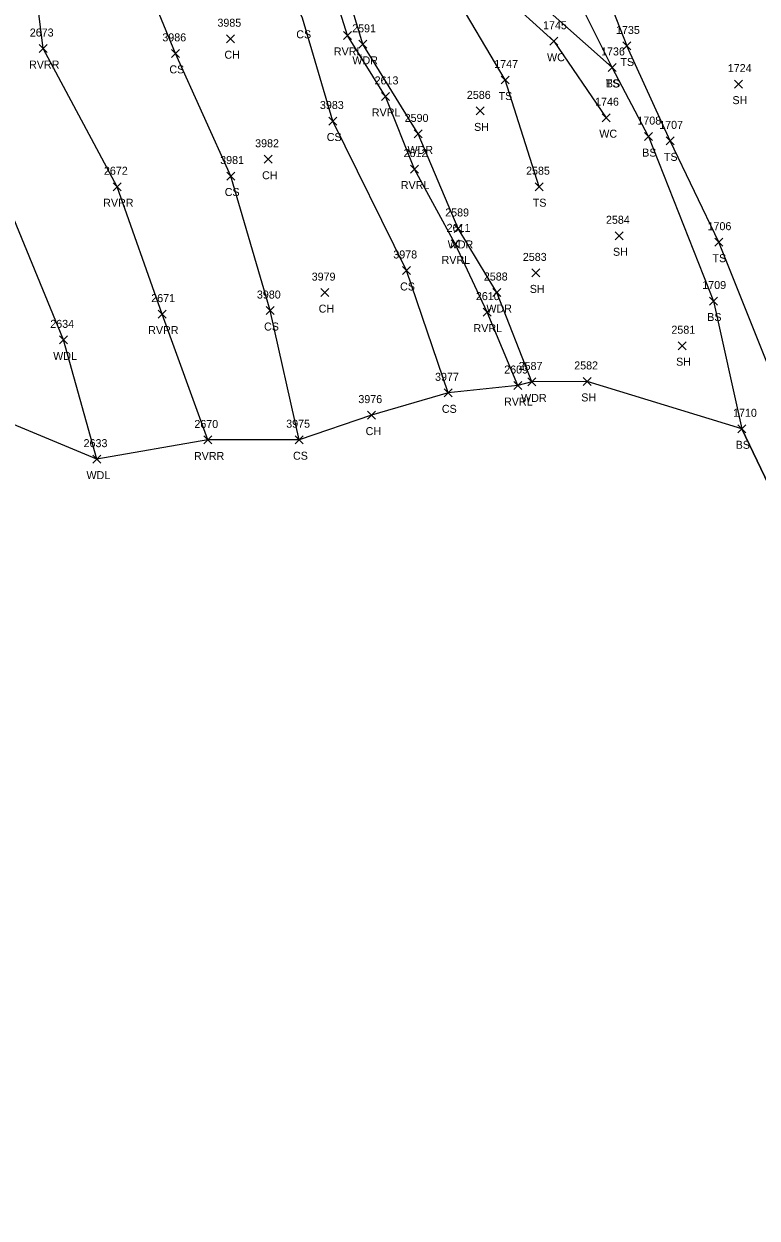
# Model space of a CAD drawing. Extents: x 1482574 to 1485769, y 580696 to 595649.
# Drawn here: x 1484896.9 to 1485080.1, y 582027 to 582325.6 of the extents above; entities that cross this region are included whole.
import ezdxf

# ---------------------------------------------------------------- set-up
doc = ezdxf.new("R2010")
doc.units = 0
for name, color, linetype in [('L_A', 7, 'Continuous'), ('L_I', 7, 'Continuous'), ('L_TIC', 7, 'Continuous'), ('LAWA', 7, 'Continuous'), ('LAWE', 7, 'Continuous'), ('LELB', 7, 'Continuous'), ('LSOGP', 7, 'Continuous')]:
    doc.layers.add(name, color=color, linetype=linetype)

msp = doc.modelspace()

# ---------------------------------------------------------------- linework, layer by layer
at = {"layer": 'L_TIC'}
for points in [[(1484947.56, 582320.86), (1484949.56, 582322.86)], [(1484949.56, 582320.86), (1484947.56, 582322.86)], [(1484976.82, 582321.68), (1484978.82, 582323.68)], [(1484978.82, 582321.68), (1484976.82, 582323.68)], [(1484980.65, 582319.46), (1484982.65, 582321.46)], [(1484982.65, 582319.46), (1484980.65, 582321.46)], [(1485028.34, 582320.23), (1485030.34, 582322.23)], [(1485030.34, 582320.23), (1485028.34, 582322.23)], [(1484900.73, 582318.41), (1484902.73, 582320.41)], [(1484902.73, 582318.41), (1484900.73, 582320.41)], [(1484933.85, 582317.2), (1484935.85, 582319.2)], [(1484935.85, 582317.2), (1484933.85, 582319.2)], [(1485046.57, 582319.05), (1485048.57, 582321.05)], [(1485048.57, 582319.05), (1485046.57, 582321.05)], [(1485042.9, 582313.68), (1485044.9, 582315.68)], [(1485044.9, 582313.68), (1485042.9, 582315.68)], [(1485042.9, 582313.68), (1485044.9, 582315.68)], [(1485044.9, 582313.68), (1485042.9, 582315.68)], [(1485016.15, 582310.55), (1485018.15, 582312.54)], [(1485018.15, 582310.55), (1485016.15, 582312.54)], [(1485074.49, 582309.51), (1485076.49, 582311.51)], [(1485076.49, 582309.51), (1485074.49, 582311.51)], [(1484986.32, 582306.44), (1484988.32, 582308.44)], [(1484988.32, 582306.44), (1484986.32, 582308.44)], [(1485009.94, 582302.82), (1485011.94, 582304.82)], [(1485011.94, 582302.82), (1485009.94, 582304.82)], [(1484973.17, 582300.29), (1484975.17, 582302.29)], [(1484975.17, 582300.29), (1484973.17, 582302.29)], [(1485041.39, 582301.12), (1485043.39, 582303.12)], [(1485043.39, 582301.12), (1485041.39, 582303.12)], [(1484994.42, 582297.07), (1484996.42, 582299.07)], [(1484996.42, 582297.07), (1484994.42, 582299.07)], [(1485051.99, 582296.4), (1485053.99, 582298.4)], [(1485053.99, 582296.4), (1485051.99, 582298.4)], [(1485057.44, 582295.33), (1485059.44, 582297.33)], [(1485059.44, 582295.33), (1485057.44, 582297.33)], [(1484956.97, 582290.73), (1484958.97, 582292.73)], [(1484958.97, 582290.73), (1484956.97, 582292.73)], [(1484947.68, 582286.54), (1484949.68, 582288.54)], [(1484949.68, 582286.54), (1484947.68, 582288.54)], [(1484993.55, 582288.28), (1484995.55, 582290.28)], [(1484995.55, 582288.28), (1484993.55, 582290.28)], [(1484919.24, 582283.86), (1484921.24, 582285.86)], [(1484921.24, 582283.86), (1484919.24, 582285.86)], [(1485024.67, 582283.87), (1485026.67, 582285.87)], [(1485026.67, 582283.87), (1485024.67, 582285.87)], [(1485004.47, 582273.43), (1485006.47, 582275.43)], [(1485006.47, 582273.43), (1485004.47, 582275.43)], [(1485044.63, 582271.6), (1485046.63, 582273.6)], [(1485046.63, 582271.6), (1485044.63, 582273.6)], [(1485003.73, 582269.58), (1485005.73, 582271.58)], [(1485005.73, 582269.58), (1485003.73, 582271.58)], [(1485069.58, 582270), (1485071.58, 582272)], [(1485071.58, 582270), (1485069.58, 582272)], [(1484991.5, 582262.93), (1484993.5, 582264.93)], [(1484993.5, 582262.93), (1484991.5, 582264.93)], [(1485023.86, 582262.32), (1485025.86, 582264.32)], [(1485025.86, 582262.32), (1485023.86, 582264.32)], [(1484971.12, 582257.39), (1484973.12, 582259.39)], [(1484973.12, 582257.39), (1484971.12, 582259.39)], [(1485014.12, 582257.42), (1485016.12, 582259.42)], [(1485016.12, 582257.42), (1485014.12, 582259.42)], [(1485068.22, 582255.29), (1485070.22, 582257.29)], [(1485070.22, 582255.29), (1485068.22, 582257.29)], [(1484930.5, 582252.02), (1484932.5, 582254.02)], [(1484932.5, 582252.02), (1484930.5, 582254.02)], [(1484957.51, 582252.91), (1484959.51, 582254.91)], [(1484959.51, 582252.91), (1484957.51, 582254.91)], [(1485011.7, 582252.51), (1485013.7, 582254.51)], [(1485013.7, 582252.51), (1485011.7, 582254.51)], [(1484905.84, 582245.58), (1484907.84, 582247.58)], [(1484907.84, 582245.58), (1484905.84, 582247.58)], [(1485060.41, 582244.13), (1485062.41, 582246.12)], [(1485062.41, 582244.13), (1485060.41, 582246.12)], [(1485019.35, 582234.16), (1485021.35, 582236.16)], [(1485021.35, 582234.16), (1485019.35, 582236.16)], [(1485022.81, 582235.06), (1485024.81, 582237.06)], [(1485024.81, 582235.06), (1485022.81, 582237.06)], [(1485036.7, 582235.19), (1485038.7, 582237.19)], [(1485038.7, 582235.19), (1485036.7, 582237.19)], [(1485001.93, 582232.34), (1485003.93, 582234.34)], [(1485003.93, 582232.34), (1485001.93, 582234.34)], [(1484982.83, 582226.77), (1484984.83, 582228.77)], [(1484984.83, 582226.77), (1484982.83, 582228.77)], [(1485075.34, 582223.35), (1485077.34, 582225.35)], [(1485077.34, 582223.35), (1485075.34, 582225.35)], [(1484941.93, 582220.55), (1484943.93, 582222.55)], [(1484943.93, 582220.55), (1484941.93, 582222.55)], [(1484964.74, 582220.62), (1484966.74, 582222.62)], [(1484966.74, 582220.62), (1484964.74, 582222.62)], [(1484914.16, 582215.76), (1484916.16, 582217.76)], [(1484916.16, 582215.76), (1484914.16, 582217.76)]]:
    msp.add_lwpolyline(points, dxfattribs=at)
at = {"layer": 'LAWA'}
for points in [[(1485023.81, 582236.06), (1485015.12, 582258.42), (1485005.47, 582274.43), (1484995.42, 582298.07), (1484981.65, 582320.46), (1484973.98, 582346.03), (1484961.86, 582366.04), (1484949.53, 582391.22), (1484938.73, 582409.53), (1484924.38, 582433.81), (1484906.56, 582452.88)], [(1484915.16, 582216.76), (1484906.84, 582246.58), (1484892.49, 582281.5), (1484876.39, 582314.59), (1484858.76, 582351.32), (1484838.48, 582391.2), (1484818.67, 582426.5), (1484807.83, 582443.63)]]:
    msp.add_lwpolyline(points, dxfattribs=at)
at = {"layer": 'LAWE'}
for points in [[(1485020.35, 582235.16), (1485012.7, 582253.51), (1485004.73, 582270.58), (1484994.55, 582289.28), (1484987.31, 582307.44), (1484977.82, 582322.68), (1484970.4, 582346.35), (1484957.22, 582366.89), (1484945.65, 582388.18), (1484936.96, 582403.16), (1484923.38, 582428.1), (1484911.63, 582446.6), (1484904.31, 582452.08)], [(1484977.46, 582379.88), (1485003.21, 582345.02), (1485029.34, 582321.23), (1485042.39, 582302.12)], [(1484942.93, 582221.55), (1484931.5, 582253.02), (1484920.25, 582284.86), (1484901.73, 582319.41), (1484898.14, 582348.38)]]:
    msp.add_lwpolyline(points, dxfattribs=at)
at = {"layer": 'LELB'}
for points in [[(1485002.93, 582233.34), (1484992.5, 582263.93), (1484974.17, 582301.29), (1484966.56, 582326.96), (1484946.25, 582370.69), (1484927.92, 582401.38), (1484904.71, 582441.25), (1484886.96, 582465.01), (1484858.7, 582503.29), (1484852.02, 582537.03), (1484804.34, 582588.15), (1484752.2, 582627.41), (1484731.88, 582664.77), (1484681.4, 582685.05), (1484649.84, 582708.59), (1484625.24, 582730.73), (1484593.85, 582761.39), (1484564.6, 582801.05), (1484536.81, 582827.49)], [(1485002.53, 582392.57), (1485034.66, 582353.07), (1485047.57, 582320.05)], [(1485017.15, 582311.55), (1485003.78, 582334.32), (1484985.61, 582358.89), (1484962.85, 582388.82)], [(1485043.9, 582314.68), (1485026.53, 582349.61), (1485014.62, 582359.21), (1484998.89, 582387.52)], [(1485043.9, 582314.68), (1485023.91, 582332.53), (1485000.78, 582361.48), (1484980.33, 582382.21)], [(1484965.74, 582221.62), (1484958.51, 582253.91), (1484948.68, 582287.54), (1484934.85, 582318.2), (1484920.86, 582352.28)], [(1485058.44, 582296.33), (1485047.57, 582320.05)], [(1485052.99, 582297.4), (1485043.9, 582314.68)], [(1485025.67, 582284.87), (1485017.15, 582311.55)], [(1485052.99, 582297.4), (1485069.22, 582256.29), (1485076.34, 582224.35), (1485082.94, 582210.46), (1485096.07, 582206.64), (1485098.2, 582187.45), (1485102.93, 582160.58), (1485107.96, 582132.69), (1485108.85, 582102.09), (1485096.78, 582056.69)], [(1485103.5, 582060.8), (1485108.92, 582082.88), (1485113.47, 582095.56), (1485110.72, 582113.13), (1485110.89, 582132.92), (1485107.23, 582162.57), (1485101.5, 582195.46), (1485096.29, 582220.03), (1485083.37, 582238.91), (1485070.58, 582271), (1485058.44, 582296.33)]]:
    msp.add_lwpolyline(points, dxfattribs=at)
at = {"layer": 'LSOGP'}
msp.add_lwpolyline([(1485090.97, 582008.56), (1485092.08, 582036.96), (1485093.6, 582042.4), (1485096.78, 582056.69), (1485108.85, 582102.09), (1485107.96, 582132.69), (1485102.93, 582160.58), (1485098.2, 582187.45), (1485082.94, 582210.46), (1485076.34, 582224.35), (1485037.7, 582236.19), (1485023.81, 582236.06), (1485020.35, 582235.16), (1485002.93, 582233.34), (1484983.83, 582227.77), (1484965.74, 582221.62), (1484942.93, 582221.55), (1484915.16, 582216.76), (1484893.16, 582225.95)], dxfattribs=at)

# ---------------------------------------------------------------- texts
at = {"layer": 'L_A'}
for s, p in [('CS', (1484965, 582321.96)), ('CH', (1484947.05, 582316.86)), ('RVRL', (1484974.39, 582317.68)), ('RVRR', (1484898.24, 582314.41)), ('WDR', (1484979.01, 582315.46)), ('WC', (1485027.65, 582316.23)), ('TS', (1485045.98, 582315.05)), ('CS', (1484933.29, 582313.2)), ('TS', (1485042.31, 582309.68)), ('BS', (1485042.34, 582309.68)), ('TS', (1485015.56, 582306.55)), ('SH', (1485073.98, 582305.51)), ('RVRL', (1484983.88, 582302.44)), ('SH', (1485009.43, 582298.82)), ('CS', (1484972.61, 582296.29)), ('WC', (1485040.7, 582297.12)), ('WDR', (1484992.78, 582293.07)), ('BS', (1485051.43, 582292.39)), ('TS', (1485056.85, 582291.33)), ('CH', (1484956.46, 582286.73)), ('RVRL', (1484991.12, 582284.28)), ('CS', (1484947.12, 582282.54)), ('RVRR', (1484916.76, 582279.86)), ('TS', (1485024.08, 582279.87)), ('WDR', (1485002.83, 582269.43)), ('SH', (1485044.12, 582267.6)), ('TS', (1485068.99, 582266)), ('RVRL', (1485001.3, 582265.58)), ('CS', (1484990.94, 582258.93)), ('SH', (1485023.34, 582258.32)), ('CH', (1484970.6, 582253.39)), ('WDR', (1485012.49, 582253.42)), ('BS', (1485067.66, 582251.29)), ('RVRR', (1484928.01, 582248.02)), ('CS', (1484956.95, 582248.91)), ('RVRL', (1485009.27, 582248.51)), ('WDL', (1484904.26, 582241.58)), ('SH', (1485059.9, 582240.12)), ('RVRL', (1485016.91, 582230.16)), ('WDR', (1485021.17, 582231.06)), ('SH', (1485036.19, 582231.19)), ('CS', (1485001.37, 582228.34)), ('CH', (1484982.32, 582222.77)), ('BS', (1485074.78, 582219.35)), ('RVRR', (1484939.44, 582216.55)), ('CS', (1484964.18, 582216.62)), ('WDL', (1484912.58, 582211.76))]:
    msp.add_text(s, height=2, dxfattribs=at).set_placement(p)
at = {"layer": 'L_I'}
for s, p in [('2673', (1484898.42, 582322.41)), ('3985', (1484945.3, 582324.86)), ('2591', (1484978.96, 582323.46)), ('1745', (1485026.65, 582324.23)), ('1735', (1485044.88, 582323.05)), ('3986', (1484931.54, 582321.2)), ('1736', (1485041.15, 582317.68)), ('1736', (1485041.15, 582317.68)), ('1747', (1485014.46, 582314.55)), ('1724', (1485072.8, 582313.51)), ('2613', (1484984.57, 582310.44)), ('2586', (1485007.62, 582306.82)), ('1746', (1485039.65, 582305.12)), ('3983', (1484970.91, 582304.29)), ('2590', (1484992.08, 582301.07)), ('1708', (1485050.22, 582300.4)), ('1707', (1485055.67, 582299.33)), ('3982', (1484954.72, 582294.73)), ('3981', (1484945.99, 582290.54)), ('2612', (1484991.81, 582292.28)), ('2672', (1484916.94, 582287.86)), ('2585', (1485022.41, 582287.87)), ('2589', (1485002.2, 582277.43)), ('2584', (1485042.37, 582275.6)), ('2611', (1485002.56, 582273.58)), ('1706', (1485067.75, 582274)), ('3978', (1484989.24, 582266.93)), ('2583', (1485021.6, 582266.32)), ('3979', (1484968.85, 582261.39)), ('2588', (1485011.86, 582261.42)), ('3980', (1484955.16, 582256.91)), ('1709', (1485066.44, 582259.29)), ('2671', (1484928.76, 582256.02)), ('2610', (1485009.87, 582256.51)), ('2634', (1484903.54, 582249.58)), ('2581', (1485058.72, 582248.12)), ('2587', (1485020.55, 582239.06)), ('2582', (1485034.44, 582239.19)), ('3977', (1484999.67, 582236.34)), ('2609', (1485016.95, 582238.16)), ('3976', (1484980.51, 582230.77)), ('1710', (1485074.13, 582227.35)), ('2670', (1484939.54, 582224.55)), ('3975', (1484962.48, 582224.62)), ('2633', (1484911.86, 582219.76))]:
    msp.add_text(s, height=2, dxfattribs=at).set_placement(p)

doc.saveas('drawing.dxf')
